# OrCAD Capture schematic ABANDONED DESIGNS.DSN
size A
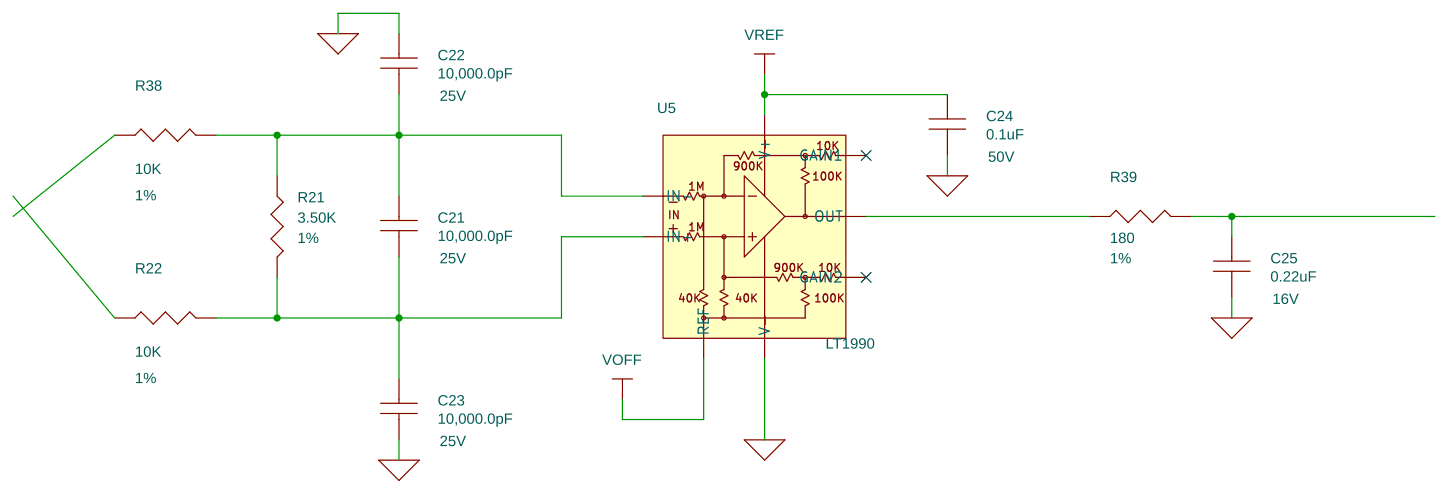
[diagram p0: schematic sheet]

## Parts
C21  10,000.0pF  [CAPC2012X88N]
C22  10,000.0pF  [CAPC2012X88N]
C23  10,000.0pF  [CAPC2012X88N]
C24  0.1uF  [CAPC2013X94N]
C25  0.22uF
R21  3.50K  [RESC2012X50N]
R22  10K  [RESC2012X50N]
R38  10K  [RESC2012X50N]
R39  180
U5  LT1990

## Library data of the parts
C21-C23 = CAP: CAP CER 10000PF 25V X7R 0805; CLASS: DISCRETE; Dielectric Type: Ceramic; Manufacturer: Kemet; Manufacturer PN: C0805C103K3RAC; PART_NUMBER: C0805C103K3RAC; Package Size: 0805; Rated Voltage: 25V; Temperature Coefficient: X7R; Tolerance: 10%
C24 = CAP: CAP CER 0.1UF 50V 5% X7R 0805; CLASS: DISCRETE; Dielectric Type: Capacitors; Manufacturer: AVX Corporation; Manufacturer PN: 08055C104JAT2A; PART_NUMBER: 08055C104JAT2A; Package Size: 0805 (2012 Metric); Rated Voltage: 50V; Temperature Coefficient: X7R; Tolerance: ±5%
C25 = CAP: Rated Voltage: 16V
R21 = RES: CLASS: DISCRETE; Manufacturer: Vishay; Manufacturer PN: CRCW080510K2FKEA; PART_NUMBER: CRCW080510K2FKEA; Package Size: 0805; Rated Power: 0.125W; Temperature Coefficient: 100ppm/K; Tolerance: 1%
R22 = RES: CLASS: DISCRETE; Manufacturer: Vishay; Manufacturer PN: CRCW08051K78FKEA; PART_NUMBER: CRCW08051K78FKEA; Package Size: 0805; Rated Power: 0.125W; Temperature Coefficient: 100ppm/K; Tolerance: 1%
R38 = RES: CLASS: DISCRETE; Manufacturer: Vishay; Manufacturer PN: CRCW08051K62FKEA; PART_NUMBER: CRCW08051K62FKEA; Package Size: 0805; Rated Power: 0.125W; Temperature Coefficient: 100ppm/K; Tolerance: 1%
R39 = RES: Tolerance: 1%
U5 = LT1990

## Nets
GND_SIGNAL: C25.2
GND_SYS: C22.1 C23.2 C24.2 U5.4(V-)
VOFF: U5.1(REF)
VREF: C24.1 U5.7(V+)
N59279: R39.1 U5.6(OUT)
N59375: C21.1 C22.2 R21.1 R38.2 U5.2(IN-)
N59383: C21.2 C23.1 R21.2 R22.2 U5.3(IN+)
N59555: C25.1 R39.2

Not connected (* = marked no-connect by the designer): R22 1; R38 1; U5 5(GAIN2)* 8(GAIN1)*
